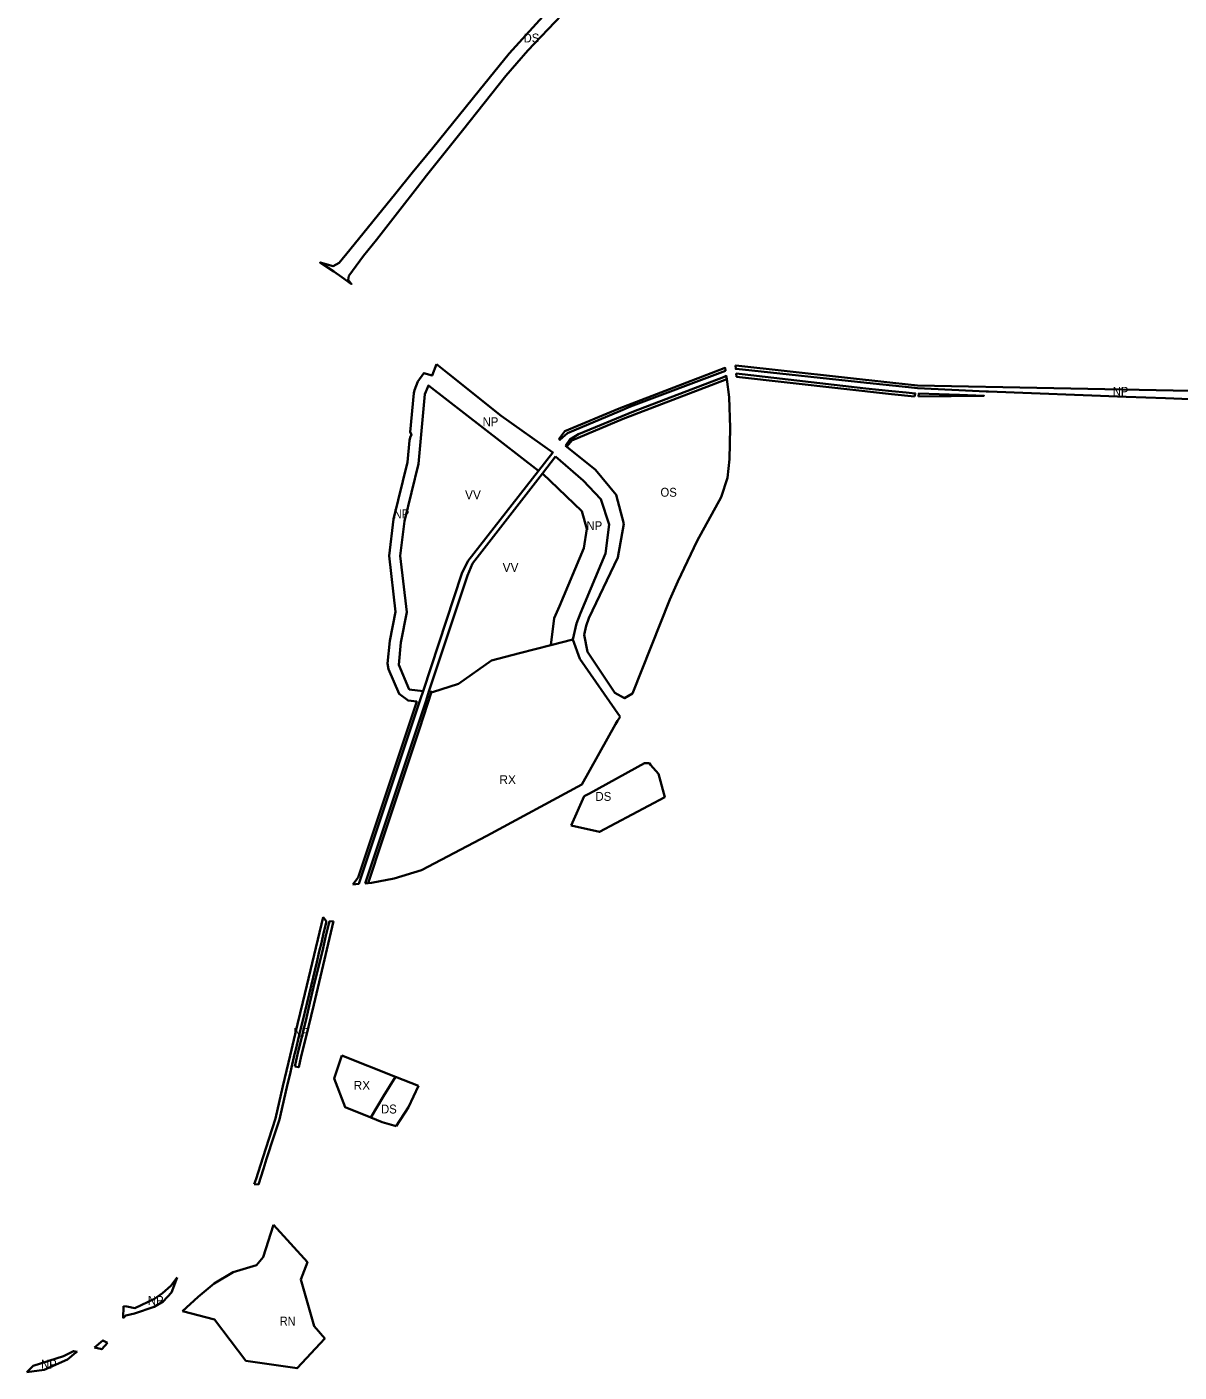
# Model space of a CAD drawing. Extents: x -650971 to -642489, y -1074311 to -1062745.
# Drawn here: x -648979 to -647426, y -1074311 to -1072500 of the extents above; entities that cross this region are included whole.
import ezdxf

# ---------------------------------------------------------------- set-up
doc = ezdxf.new("R2010")
doc.units = 0
doc.header["$LTSCALE"] = 4.8
for name, color, linetype, lineweight in [('24', 7, 'Continuous', 35), ('4', 7, 'Continuous', 35), ('45', 7, 'Continuous', 35), ('48', 7, 'Continuous', 35), ('62', 7, 'Continuous', 35), ('7', 7, 'Continuous', 35), ('9', 7, 'Continuous', 35)]:
    doc.layers.add(name, color=color, linetype=linetype, lineweight=lineweight)

msp = doc.modelspace()

# ---------------------------------------------------------------- linework, layer by layer
at = {"layer": '24'}
for points in [[(-648274.53, -1072476.196), (-648328.847, -1072535.816), (-648369.37, -1072585.645), (-648431.557, -1072662.77), (-648459.243, -1072696.417), (-648481.468, -1072723.736), (-648543.255, -1072800.016), (-648557.588, -1072817.727), (-648565.726, -1072822.048), (-648583.407, -1072817.256), (-648564.86, -1072829.45), (-648554.22, -1072836.89), (-648541.102, -1072846.281), (-648545.462, -1072840.329), (-648544.632, -1072835.177), (-648524.979, -1072808.383), (-648507.503, -1072786.605), (-648476.204, -1072746.1), (-648452.274, -1072715.637), (-648439.912, -1072699.826), (-648391.796, -1072639.344), (-648333.178, -1072565.837), (-648303.791, -1072531.792), (-648258.165, -1072484.283)], [(-648245.341, -1073575.152), (-648227.63, -1073535.89), (-648220.42, -1073532.43), (-648146.4, -1073491.55), (-648139.56, -1073491.4)], [(-648139.56, -1073491.4), (-648138.41, -1073493.62), (-648127.31, -1073505.75)], [(-648127.31, -1073505.75), (-648119, -1073537), (-648207, -1073584), (-648245.341, -1073575.152)], [(-648515.333, -1073968.584), (-648498, -1073940), (-648481.749, -1073913.76), (-648451.05, -1073925.87)], [(-648451.05, -1073925.87), (-648464.44, -1073954.69), (-648480.86, -1073980.25)], [(-648480.86, -1073980.25), (-648499.84, -1073974.76), (-648515.333, -1073968.584)]]:
    msp.add_lwpolyline(points, dxfattribs=at)
at = {"layer": '4'}
msp.add_line((-648554.42, -1073885.092), (-648481.749, -1073913.76), dxfattribs=at)
for points in [[(-648433.206, -1073395.51), (-648432.187, -1073395.625), (-648397.062, -1073384.375), (-648352.312, -1073353), (-648314.687, -1073343.25), (-648272.642, -1073332.558), (-648243.08, -1073325.04)], [(-648243.08, -1073325.04), (-648233.36, -1073350.68), (-648179.07, -1073428.81)], [(-648518.867, -1073652.836), (-648499.399, -1073594.679), (-648449.599, -1073445.278), (-648433.206, -1073395.51)], [(-648179.07, -1073428.81), (-648182.81, -1073434.38), (-648185.34, -1073438.91), (-648230.81, -1073520.18), (-648358.69, -1073589.35), (-648447.06, -1073635.39), (-648483.58, -1073646.7), (-648514.23, -1073652.37), (-648518.867, -1073652.836)], [(-648515.333, -1073968.584), (-648549.76, -1073954.86), (-648564.75, -1073915.91), (-648554.42, -1073885.092)], [(-648481.749, -1073913.76), (-648498, -1073940), (-648515.333, -1073968.584)]]:
    msp.add_lwpolyline(points, dxfattribs=at)
at = {"layer": '45'}
for points in [[(-648444.523, -1073394.235), (-648463.25, -1073392.125), (-648477.562, -1073358.875), (-648474.5, -1073328.75), (-648466.687, -1073288.25), (-648475.437, -1073212.375), (-648469.875, -1073165.5), (-648450.875, -1073088.375), (-648442.187, -1072994.5), (-648437.643, -1072982.601), (-648289.148, -1073097.66)], [(-648289.148, -1073097.66), (-648384.6, -1073219.54), (-648392.43, -1073235.98), (-648444.523, -1073394.235)], [(-648436.857, -1073395.099), (-648385.09, -1073238.58), (-648378.17, -1073222.67), (-648283.884, -1073101.15)], [(-648283.884, -1073101.15), (-648231, -1073152), (-648224, -1073176), (-648228, -1073202), (-648261, -1073280), (-648268, -1073296), (-648272.642, -1073332.558)], [(-648272.642, -1073332.558), (-648314.687, -1073343.25), (-648352.312, -1073353), (-648397.062, -1073384.375), (-648432.187, -1073395.625), (-648433.206, -1073395.51), (-648436.857, -1073395.099)]]:
    msp.add_lwpolyline(points, dxfattribs=at)
at = {"layer": '48'}
for p, q in [((-648283.884, -1073101.15), (-648266.38, -1073078.59)), ((-648848.696, -1074238.993), (-648848.28, -1074222.49))]:
    msp.add_line(p, q, dxfattribs=at)
for points in [[(-648023.818, -1072955.949), (-648023.495, -1072955.875), (-647811.752, -1072979.4), (-647778.296, -1072982.767), (-647411.293, -1072989.813), (-647395.47, -1072993.25), (-647388.62, -1072948.03), (-647394.87, -1072936.08), (-647387.64, -1072868.69), (-647375.92, -1072833.99), (-647331.82, -1072854.49), (-647284.75, -1072877.79)], [(-648539.599, -1073654.802), (-648532.252, -1073645.567), (-648513.627, -1073589.927), (-648463.838, -1073440.559), (-648453.228, -1073408.349), (-648464.929, -1073407.031), (-648477.028, -1073398.055), (-648491.34, -1073364.805), (-648492.485, -1073357.358), (-648489.355, -1073326.567), (-648481.853, -1073287.675), (-648490.539, -1073212.35), (-648484.661, -1073162.812), (-648465.708, -1073085.876), (-648463.036, -1073057.011), (-648461.973, -1073052.688), (-648460.355, -1073048.753), (-648461.979, -1073045.585), (-648457.123, -1072993.118), (-648456.2, -1072989.149), (-648451.657, -1072977.25), (-648443.591, -1072965.983), (-648432.527, -1072969.463), (-648426.547, -1072954.108)], [(-648426.547, -1072954.108), (-648411.09, -1072966.5), (-648339.58, -1073023.82), (-648269.78, -1073072.93), (-648289.148, -1073097.66)], [(-647153.44, -1073058.06), (-647213.99, -1073041.449), (-647353.78, -1073003.1), (-647367.45, -1073002.47), (-647394.46, -1073001.23), (-647400.55, -1073001.48), (-647402.49, -1073001.41), (-647411.324, -1073001.08), (-647444.42, -1072999.87), (-647497.35, -1072997.93), (-647682.74, -1072990.95), (-647686.14, -1072990.78), (-647778.3, -1072986.29), (-647790.52, -1072985.06), (-647846.85, -1072979.37), (-648014.16, -1072961.36), (-648023.37, -1072960.37), (-648023.818, -1072955.949)], [(-648261.902, -1073054.939), (-648253.635, -1073044.348), (-648180.651, -1073013.629), (-648038.877, -1072959.418), (-648037.595, -1072959.123), (-648037.17, -1072963.24)], [(-648037.17, -1072963.24), (-648165.13, -1073011.22), (-648178.89, -1073017.03), (-648250.04, -1073047.08), (-648260.27, -1073056.17), (-648261.902, -1073054.939)], [(-648252.64, -1073064.13), (-648247.16, -1073055.34), (-648235.47, -1073048.4), (-648161.07, -1073017.9), (-648040.06, -1072971.47), (-648036.2, -1072969.98), (-648035.592, -1072974.222)], [(-648035.592, -1072974.222), (-648175.061, -1073027.551), (-648244.214, -1073056.657), (-648250.491, -1073064.698), (-648251.027, -1073065.418), (-648252.64, -1073064.13)], [(-648022.74, -1072966.57), (-648014.58, -1072967.51), (-647848.15, -1072986.63), (-647813.2, -1072990.26), (-647793.59, -1072992.29), (-647781.65, -1072993.53), (-647782.72, -1072997.397)], [(-647782.72, -1072997.397), (-647813.331, -1072994.317), (-648022.279, -1072971.102), (-648022.74, -1072966.57)], [(-648289.148, -1073097.66), (-648437.643, -1072982.601), (-648442.187, -1072994.5), (-648450.875, -1073088.375), (-648469.875, -1073165.5), (-648475.437, -1073212.375), (-648466.687, -1073288.25), (-648474.5, -1073328.75), (-648477.562, -1073358.875), (-648463.25, -1073392.125), (-648444.523, -1073394.235)], [(-648266.38, -1073078.59), (-648228.91, -1073110.54), (-648205.04, -1073136.07), (-648194.2, -1073170.13), (-648198.7, -1073209.08), (-648232.64, -1073289.31), (-648237.98, -1073303.4), (-648243.08, -1073325.04), (-648272.642, -1073332.558)], [(-648272.642, -1073332.558), (-648268, -1073296), (-648261, -1073280), (-648228, -1073202), (-648224, -1073176), (-648231, -1073152), (-648283.884, -1073101.15)], [(-648444.523, -1073394.235), (-648448.05, -1073404.95), (-648531.31, -1073654.08), (-648539.599, -1073654.802)], [(-648522.79, -1073653.23), (-648517.47, -1073637.26), (-648440.74, -1073406.84), (-648436.857, -1073395.099), (-648433.206, -1073395.51)], [(-648433.206, -1073395.51), (-648449.599, -1073445.278), (-648499.399, -1073594.679), (-648518.867, -1073652.836), (-648522.79, -1073653.23)], [(-648672.336, -1074058.391), (-648669.584, -1074051.005), (-648660.613, -1074022.822), (-648647.944, -1073983.639), (-648643.415, -1073969.782), (-648633.591, -1073926.228), (-648623.827, -1073884.957), (-648613.86, -1073842.943), (-648606.633, -1073813.202), (-648601.309, -1073790.592), (-648579.272, -1073698.648)], [(-648579.272, -1073698.648), (-648574.99, -1073704.67), (-648578.69, -1073720.11), (-648581.82, -1073733.14), (-648584.69, -1073745.15), (-648588.06, -1073759.19), (-648595.71, -1073791.1), (-648607.4, -1073839.84), (-648607.72, -1073841.19), (-648611.69, -1073857.74), (-648616.76, -1073878.91), (-648617.77, -1073883.09), (-648622.06, -1073901.02), (-648623.58, -1073907.34), (-648628.21, -1073927.61), (-648636.34, -1073963.19), (-648638.15, -1073971.13), (-648645.7, -1073994.3), (-648655.5, -1074024.36), (-648659.85, -1074037.72), (-648666.67, -1074058.64), (-648672.336, -1074058.391)], [(-648617.72, -1073900.06), (-648613.78, -1073883.59), (-648606.83, -1073854.48), (-648601.98, -1073834.2), (-648597.23, -1073814.32), (-648592.17, -1073793.18), (-648579.57, -1073740.47), (-648576.05, -1073725.82), (-648573.46, -1073714.88), (-648571.72, -1073707.63), (-648570.99, -1073704.56), (-648565.224, -1073704.393)], [(-648565.224, -1073704.393), (-648586.715, -1073794.059), (-648592.044, -1073816.692), (-648599.275, -1073846.445), (-648609.231, -1073888.415), (-648612.186, -1073900.905), (-648617.72, -1073900.06)], [(-648775.93, -1074183.91), (-648783.863, -1074204.056), (-648794.902, -1074216.219), (-648807.065, -1074223.704), (-648833.449, -1074232.685), (-648845.424, -1074235.305), (-648848.696, -1074238.993)], [(-648848.28, -1074222.49), (-648844.05, -1074223.24), (-648833.11, -1074225.2), (-648806.55, -1074212.62), (-648795.65, -1074205.35), (-648784.8, -1074195.26), (-648775.93, -1074183.91)], [(-648887.619, -1074278.134), (-648876.21, -1074268.73), (-648870.041, -1074271.933)], [(-648870.041, -1074271.933), (-648877.799, -1074280.64), (-648887.619, -1074278.134)], [(-648978.575, -1074311.426), (-648970.3, -1074302.9), (-648929.03, -1074290.14), (-648915.73, -1074283.08), (-648910.988, -1074284.211)], [(-648910.988, -1074284.211), (-648912.63, -1074284.912), (-648923.698, -1074294.313), (-648955.265, -1074308.325), (-648978.575, -1074311.426)]]:
    msp.add_lwpolyline(points, dxfattribs=at)
msp.add_lwpolyline([(-647777.336, -1072997.711), (-647776.77, -1072993.69), (-647721.83, -1072995.45), (-647689.11, -1072996.49)], close=True, dxfattribs=at)
at = {"layer": '7'}
for points in [[(-648768.94, -1074229.25), (-648747.74, -1074210.12), (-648726.23, -1074192.02), (-648700.45, -1074176.73), (-648669.01, -1074167.27), (-648660.16, -1074156.75), (-648646.42, -1074113.19)], [(-648646.42, -1074113.19), (-648600.53, -1074163.47), (-648609.49, -1074186.61), (-648591.67, -1074249.72), (-648577.25, -1074266.06), (-648614.6, -1074306.17), (-648683.5, -1074296.12), (-648725.93, -1074240.58), (-648768.94, -1074229.25)]]:
    msp.add_lwpolyline(points, dxfattribs=at)
at = {"layer": '9'}
for points in [[(-648251.027, -1073065.418), (-648250.491, -1073064.698), (-648244.214, -1073056.657), (-648175.061, -1073027.551), (-648035.592, -1072974.222)], [(-648035.592, -1072974.222), (-648032.09, -1072998.65), (-648030.86, -1073039.71), (-648031.8, -1073082.07), (-648034.43, -1073107.07), (-648043.29, -1073132.97), (-648075.34, -1073191.93), (-648101.67, -1073246.63), (-648112.36, -1073270.87), (-648162.55, -1073397.4), (-648173.38, -1073404.03), (-648186.47, -1073396.47)], [(-648186.47, -1073396.47), (-648223.03, -1073341.59), (-648227.75, -1073318.75), (-648224.86, -1073306.66), (-648221.39, -1073296.24), (-648182.12, -1073214.56), (-648174.03, -1073168.94), (-648184.37, -1073129.89), (-648212.22, -1073096.39), (-648251.027, -1073065.418)]]:
    msp.add_lwpolyline(points, dxfattribs=at)

# ---------------------------------------------------------------- texts
at = {"layer": '62'}
for s, width, p in [('DS', 0.95, (-648309.284, -1072520.858)), ('NP', 0.95, (-647515.505, -1072996.594)), ('NP', 0.95, (-648364.505, -1073037.594)), ('OS', 0.95, (-648124.882, -1073132.612)), ('NP', 0.95, (-648484.505, -1073161.594)), ('NP', 0.95, (-648224.505, -1073177.594)), ('DS', 0.95, (-648212.386, -1073542.148)), ('NP', 0.95, (-648619.524, -1073859.849)), ('DS', 0.95, (-648501.386, -1073963.148)), ('NP', 0.95, (-648815.524, -1074220.849)), ('RN', 0.9, (-648637.627, -1074248.756)), ('NP', 0.95, (-648959.524, -1074306.849))]:
    msp.add_text(s, height=12, dxfattribs=dict(at, width=width)).set_placement(p)
for s, p in [('VV', (-648388.203, -1073135.952)), ('VV', (-648337.553, -1073233.772)), ('RX', (-648341.882, -1073519.612)), ('RX', (-648538.32, -1073931.277))]:
    msp.add_text(s, height=12, dxfattribs=at).set_placement(p)

doc.saveas('drawing.dxf')
